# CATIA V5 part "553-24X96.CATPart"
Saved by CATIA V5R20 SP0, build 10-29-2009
Part number: 553-24X96
Definition: NONE
Nomenclature: 553-24X96
Source: Unknown
Description: 553-24X96
Bounding box of the stored display mesh (mm): x 0 to 96, y -17.5 to 17.5, z -17.5 to 17.5
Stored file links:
  C:\Users\Utente\Desktop\IO LAVORO\3D X SITO CF\X SITO\PLASTICA\553\553-24X96.CATPart
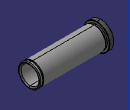
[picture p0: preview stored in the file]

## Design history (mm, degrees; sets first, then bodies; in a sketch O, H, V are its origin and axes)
Body1 "553-24X96" (main body)
  Solid1: solid without history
